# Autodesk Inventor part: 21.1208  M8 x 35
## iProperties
Created: 2006-02
Part Number: 21.1208  M8 x 35
Material: Steel, Mild
Description: Cylinder Head Cap Screw
Document SubType Name: Modeling
Standard: DIN 7984
Designer: Andy Moles
Standards Organization: DIN
Language: en-US
Size Designation: M8 x 35
Categories: <MemberInstance><Categories><Category DisplayName="Fasteners" InternalName="e4da775c-781d-43d5-af7c-5136215cf5a6" Mnemonic="FSTN"><Category DisplayName="Bolts"
Density: 7.86 g/cm^3
Mass: 18.1893 g
Surface Area: 13.9466 cm^2
Volume: 2.31416 cm^3
Author: Andy Moles
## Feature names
1. Body [Revolution]
2. Slot [Extrusion]
3. Fillet1
4. Chamfer1
